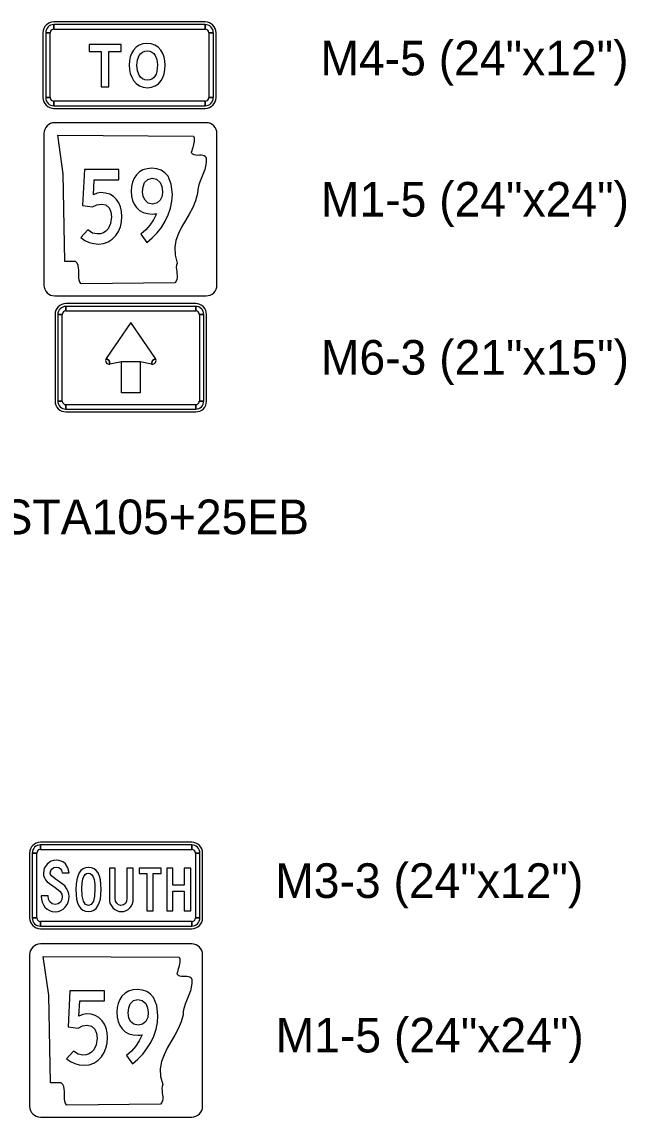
# Model space of a CAD drawing. Extents: x 620856.8 to 620948.6, y 415598.8 to 415658.2.
# Drawn here: x 620865.53 to 620872.52, y 415643.04 to 415655.69 of the extents above; entities that cross this region are included whole.
import ezdxf

# ---------------------------------------------------------------- set-up
doc = ezdxf.new("R2010")
doc.units = 0
doc.layers.add('SIGNS', color=7, linetype='Continuous')

msp = doc.modelspace()

# ---------------------------------------------------------------- linework, layer by layer
at = {"layer": 'SIGNS'}
for p, q in [((620867.653, 415655.689), (620865.903, 415655.689)), ((620865.778, 415655.564), (620865.778, 415654.814)), ((620865.81, 415655.564), (620865.862, 415655.564)), ((620865.903, 415655.605), (620865.903, 415655.657)), ((620867.653, 415655.657), (620867.653, 415655.605)), ((620867.695, 415655.564), (620867.747, 415655.564)), ((620867.778, 415654.814), (620867.778, 415655.564)), ((620865.862, 415654.814), (620865.81, 415654.814)), ((620867.747, 415654.814), (620867.695, 415654.814)), ((620865.903, 415654.72), (620865.903, 415654.772)), ((620865.903, 415654.689), (620867.653, 415654.689)), ((620867.653, 415654.772), (620867.653, 415654.72)), ((620867.664, 415654.524), (620865.914, 415654.524)), ((620865.789, 415654.399), (620865.789, 415652.649)), ((620867.789, 415652.649), (620867.789, 415654.399)), ((620865.789, 415652.649), (620865.789, 415652.649)), ((620865.914, 415652.524), (620867.664, 415652.524)), ((620867.543, 415652.434), (620866.043, 415652.434)), ((620866.043, 415652.35), (620866.043, 415652.402)), ((620867.543, 415652.402), (620867.543, 415652.35)), ((620865.918, 415652.309), (620865.918, 415651.309)), ((620865.949, 415652.309), (620866.001, 415652.309)), ((620867.585, 415652.309), (620867.637, 415652.309)), ((620867.668, 415651.309), (620867.668, 415652.309)), ((620866.543, 415651.777), (620866.508, 415651.8)), ((620866.552, 415651.737), (620866.543, 415651.777)), ((620867.043, 415651.777), (620867.034, 415651.737)), ((620867.078, 415651.8), (620867.043, 415651.777)), ((620866.001, 415651.309), (620865.949, 415651.309)), ((620866.043, 415651.215), (620866.043, 415651.267)), ((620867.543, 415651.267), (620867.543, 415651.215)), ((620867.637, 415651.309), (620867.585, 415651.309)), ((620866.043, 415651.184), (620867.543, 415651.184)), ((620867.498, 415646.213), (620865.748, 415646.213)), ((620865.748, 415646.13), (620865.748, 415646.182)), ((620867.498, 415646.182), (620867.498, 415646.13)), ((620865.623, 415646.088), (620865.623, 415645.338)), ((620865.654, 415646.088), (620865.707, 415646.088)), ((620867.54, 415646.088), (620867.592, 415646.088)), ((620867.623, 415645.338), (620867.623, 415646.088)), ((620865.707, 415645.338), (620865.654, 415645.338)), ((620865.748, 415645.244), (620865.748, 415645.296)), ((620867.498, 415645.296), (620867.498, 415645.244)), ((620867.592, 415645.338), (620867.54, 415645.338)), ((620865.748, 415645.213), (620867.498, 415645.213)), ((620867.498, 415645.037), (620865.748, 415645.037)), ((620865.623, 415644.912), (620865.623, 415643.162)), ((620867.623, 415643.162), (620867.623, 415644.912)), ((620865.623, 415643.162), (620865.623, 415643.162)), ((620865.748, 415643.037), (620867.498, 415643.037))]:
    msp.add_line(p, q, dxfattribs=at)
for points in [[(620865.81, 415655.564), (620865.81, 415654.814), (620865.862, 415654.814), (620865.862, 415655.564), (620865.81, 415655.564), (620865.81, 415655.564)], [(620867.653, 415655.657), (620865.903, 415655.657), (620865.903, 415655.605), (620867.653, 415655.605), (620867.653, 415655.657), (620867.653, 415655.657)], [(620867.747, 415654.814), (620867.747, 415655.564), (620867.695, 415655.564), (620867.695, 415654.814), (620867.747, 415654.814), (620867.747, 415654.814)], [(620866.451, 415654.939), (620866.538, 415654.939), (620866.538, 415655.347), (620866.681, 415655.347), (620866.681, 415655.429), (620866.31, 415655.429), (620866.31, 415655.347), (620866.451, 415655.347)], [(620865.903, 415654.72), (620867.653, 415654.72), (620867.653, 415654.772), (620865.903, 415654.772), (620865.903, 415654.72), (620865.903, 415654.72)], [(620867.519, 415654.37), (620867.524, 415654.351), (620867.525, 415654.331), (620867.525, 415654.312), (620867.522, 415654.293), (620867.518, 415654.274), (620867.514, 415654.255), (620867.508, 415654.236), (620867.502, 415654.218), (620867.497, 415654.199), (620867.492, 415654.181), (620867.506, 415654.165), (620867.523, 415654.156), (620867.543, 415654.152), (620867.565, 415654.151), (620867.586, 415654.152), (620867.607, 415654.152), (620867.626, 415654.15), (620867.642, 415654.144), (620867.655, 415654.132), (620867.663, 415654.112), (620867.664, 415654.066), (620867.658, 415654.024), (620867.648, 415653.983), (620867.633, 415653.945), (620867.618, 415653.906), (620867.602, 415653.869), (620867.587, 415653.83), (620867.575, 415653.79), (620867.566, 415653.749), (620867.564, 415653.705), (620867.542, 415653.623), (620867.508, 415653.544), (620867.468, 415653.469), (620867.424, 415653.394), (620867.38, 415653.319), (620867.343, 415653.243), (620867.315, 415653.165), (620867.3, 415653.082), (620867.304, 415652.995), (620867.329, 415652.901), (620867.322, 415652.878), (620867.319, 415652.854), (620867.32, 415652.83), (620867.323, 415652.806), (620867.326, 415652.782), (620867.329, 415652.759), (620867.329, 415652.736), (620867.326, 415652.714), (620867.318, 415652.693), (620867.302, 415652.673), (620866.219, 415652.663), (620866.204, 415652.683), (620866.195, 415652.707), (620866.192, 415652.733), (620866.191, 415652.761), (620866.192, 415652.791), (620866.192, 415652.82), (620866.19, 415652.849), (620866.185, 415652.876), (620866.174, 415652.901), (620866.155, 415652.921), (620866.029, 415652.921), (620866.011, 415653.933), (620865.948, 415654.38), (620867.519, 415654.37), (620867.519, 415654.37)], [(620866.214, 415653.198), (620866.262, 415653.165), (620866.312, 415653.142), (620866.364, 415653.128), (620866.419, 415653.123), (620866.478, 415653.129), (620866.531, 415653.147), (620866.578, 415653.178), (620866.619, 415653.221), (620866.65, 415653.268), (620866.672, 415653.321), (620866.685, 415653.379), (620866.689, 415653.442), (620866.685, 415653.499), (620866.674, 415653.551), (620866.655, 415653.597), (620866.627, 415653.638), (620866.591, 415653.672), (620866.549, 415653.697), (620866.499, 415653.712), (620866.445, 415653.717), (620866.404, 415653.711), (620866.36, 415653.691), (620866.369, 415653.866), (620866.656, 415653.866), (620866.656, 415653.982), (620866.256, 415653.982), (620866.235, 415653.566), (620866.352, 415653.551), (620866.4, 415653.577), (620866.453, 415653.585), (620866.505, 415653.574), (620866.543, 415653.539), (620866.563, 415653.493), (620866.57, 415653.436), (620866.56, 415653.361), (620866.53, 415653.3), (620866.505, 415653.273), (620866.477, 415653.254), (620866.443, 415653.242), (620866.406, 415653.239), (620866.349, 415653.25), (620866.295, 415653.286)], [(620867.543, 415652.402), (620866.043, 415652.402), (620866.043, 415652.35), (620867.543, 415652.35), (620867.543, 415652.402), (620867.543, 415652.402)], [(620865.949, 415652.309), (620865.949, 415651.309), (620866.001, 415651.309), (620866.001, 415652.309), (620865.949, 415652.309), (620865.949, 415652.309)], [(620867.637, 415651.309), (620867.637, 415652.309), (620867.585, 415652.309), (620867.585, 415651.309), (620867.637, 415651.309), (620867.637, 415651.309)], [(620866.793, 415652.215), (620866.508, 415651.8), (620866.543, 415651.777), (620866.552, 415651.737), (620866.684, 415651.767), (620866.903, 415651.767), (620867.034, 415651.737), (620867.043, 415651.777), (620867.078, 415651.8), (620866.793, 415652.215), (620866.793, 415652.215)], [(620866.903, 415651.402), (620866.684, 415651.402), (620866.684, 415651.767), (620866.903, 415651.767), (620866.903, 415651.402), (620866.903, 415651.402)], [(620866.043, 415651.215), (620867.543, 415651.215), (620867.543, 415651.267), (620866.043, 415651.267), (620866.043, 415651.215), (620866.043, 415651.215)], [(620867.498, 415646.182), (620865.748, 415646.182), (620865.748, 415646.13), (620867.498, 415646.13), (620867.498, 415646.182), (620867.498, 415646.182)], [(620865.654, 415646.088), (620865.654, 415645.338), (620865.707, 415645.338), (620865.707, 415646.088), (620865.654, 415646.088), (620865.654, 415646.088)], [(620867.592, 415645.338), (620867.592, 415646.088), (620867.54, 415646.088), (620867.54, 415645.338), (620867.592, 415645.338), (620867.592, 415645.338)], [(620865.757, 415645.593), (620865.757, 415645.588), (620865.759, 415645.553), (620865.768, 415645.521), (620865.782, 415645.491), (620865.801, 415645.464), (620865.826, 415645.44), (620865.854, 415645.424), (620865.885, 415645.414), (620865.919, 415645.41), (620865.953, 415645.413), (620865.984, 415645.423), (620866.011, 415645.44), (620866.036, 415645.463), (620866.055, 415645.489), (620866.069, 415645.518), (620866.077, 415645.55), (620866.08, 415645.585), (620866.077, 415645.618), (620866.067, 415645.65), (620866.051, 415645.679), (620866.029, 415645.708), (620865.985, 415645.745), (620865.919, 415645.79), (620865.875, 415645.823), (620865.866, 415645.84), (620865.862, 415645.859), (620865.867, 415645.885), (620865.883, 415645.906), (620865.905, 415645.921), (620865.932, 415645.926), (620865.96, 415645.921), (620865.981, 415645.907), (620865.992, 415645.888), (620866, 415645.859), (620866.08, 415645.859), (620866.067, 415645.918), (620866.037, 415645.963), (620866.014, 415645.981), (620865.989, 415645.994), (620865.961, 415646.002), (620865.929, 415646.005), (620865.9, 415646.002), (620865.873, 415645.994), (620865.848, 415645.98), (620865.826, 415645.96), (620865.793, 415645.912), (620865.783, 415645.857), (620865.785, 415645.828), (620865.794, 415645.802), (620865.807, 415645.777), (620865.827, 415645.755), (620865.919, 415645.689), (620865.954, 415645.663), (620865.975, 415645.643), (620865.994, 415645.614), (620866.001, 415645.584), (620865.995, 415645.55), (620865.979, 415645.521), (620865.952, 415645.5), (620865.919, 415645.493), (620865.884, 415645.501), (620865.857, 415645.525), (620865.841, 415645.556), (620865.836, 415645.593)], [(620866.546, 415645.912), (620866.546, 415645.557), (620866.548, 415645.528), (620866.556, 415645.501), (620866.569, 415645.477), (620866.587, 415645.454), (620866.608, 415645.436), (620866.631, 415645.422), (620866.657, 415645.414), (620866.686, 415645.412), (620866.714, 415645.414), (620866.739, 415645.423), (620866.763, 415645.437), (620866.784, 415645.457), (620866.801, 415645.479), (620866.813, 415645.504), (620866.82, 415645.53), (620866.822, 415645.558), (620866.822, 415645.912), (620866.747, 415645.912), (620866.747, 415645.561), (620866.743, 415645.53), (620866.73, 415645.506), (620866.708, 415645.488), (620866.679, 415645.483), (620866.651, 415645.489), (620866.63, 415645.507), (620866.617, 415645.532), (620866.613, 415645.561), (620866.613, 415645.912)], [(620866.98, 415645.421), (620867.051, 415645.421), (620867.051, 415645.85), (620867.142, 415645.85), (620867.142, 415645.912), (620866.89, 415645.912), (620866.89, 415645.85), (620866.98, 415645.85)], [(620867.21, 415645.421), (620867.277, 415645.421), (620867.277, 415645.646), (620867.411, 415645.646), (620867.411, 415645.421), (620867.486, 415645.421), (620867.486, 415645.912), (620867.411, 415645.912), (620867.411, 415645.715), (620867.277, 415645.715), (620867.277, 415645.912), (620867.21, 415645.912)], [(620865.748, 415645.244), (620867.498, 415645.244), (620867.498, 415645.296), (620865.748, 415645.296), (620865.748, 415645.244), (620865.748, 415645.244)], [(620867.353, 415644.883), (620867.358, 415644.864), (620867.359, 415644.844), (620867.359, 415644.825), (620867.356, 415644.806), (620867.352, 415644.787), (620867.348, 415644.768), (620867.342, 415644.749), (620867.336, 415644.731), (620867.331, 415644.713), (620867.326, 415644.694), (620867.34, 415644.678), (620867.357, 415644.669), (620867.377, 415644.665), (620867.399, 415644.665), (620867.42, 415644.665), (620867.441, 415644.666), (620867.46, 415644.663), (620867.476, 415644.657), (620867.489, 415644.645), (620867.497, 415644.625), (620867.498, 415644.579), (620867.492, 415644.537), (620867.482, 415644.496), (620867.467, 415644.458), (620867.452, 415644.42), (620867.436, 415644.382), (620867.421, 415644.343), (620867.409, 415644.304), (620867.4, 415644.262), (620867.398, 415644.218), (620867.376, 415644.136), (620867.342, 415644.058), (620867.302, 415643.982), (620867.257, 415643.907), (620867.214, 415643.833), (620867.177, 415643.757), (620867.149, 415643.678), (620867.134, 415643.596), (620867.138, 415643.508), (620867.163, 415643.415), (620867.156, 415643.391), (620867.153, 415643.368), (620867.154, 415643.344), (620867.157, 415643.319), (620867.16, 415643.296), (620867.163, 415643.272), (620867.163, 415643.249), (620867.16, 415643.227), (620867.152, 415643.206), (620867.136, 415643.186), (620866.052, 415643.176), (620866.038, 415643.196), (620866.029, 415643.22), (620866.026, 415643.246), (620866.025, 415643.275), (620866.026, 415643.304), (620866.026, 415643.334), (620866.024, 415643.363), (620866.019, 415643.39), (620866.008, 415643.414), (620865.989, 415643.434), (620865.863, 415643.434), (620865.845, 415644.446), (620865.781, 415644.893), (620867.353, 415644.883), (620867.353, 415644.883)], [(620866.048, 415643.711), (620866.096, 415643.678), (620866.146, 415643.655), (620866.198, 415643.641), (620866.253, 415643.637), (620866.312, 415643.643), (620866.365, 415643.661), (620866.412, 415643.691), (620866.453, 415643.734), (620866.484, 415643.782), (620866.505, 415643.834), (620866.519, 415643.892), (620866.523, 415643.955), (620866.519, 415644.012), (620866.508, 415644.064), (620866.489, 415644.111), (620866.461, 415644.151), (620866.425, 415644.186), (620866.382, 415644.211), (620866.333, 415644.226), (620866.279, 415644.231), (620866.238, 415644.224), (620866.194, 415644.204), (620866.203, 415644.379), (620866.49, 415644.379), (620866.49, 415644.495), (620866.09, 415644.495), (620866.069, 415644.079), (620866.186, 415644.064), (620866.234, 415644.09), (620866.287, 415644.099), (620866.339, 415644.087), (620866.377, 415644.052), (620866.397, 415644.006), (620866.404, 415643.949), (620866.394, 415643.874), (620866.364, 415643.813), (620866.339, 415643.786), (620866.31, 415643.767), (620866.277, 415643.756), (620866.24, 415643.752), (620866.183, 415643.764), (620866.129, 415643.799)]]:
    msp.add_lwpolyline(points, close=True, dxfattribs=at)
for points in [[(620867.19, 415655.188), (620867.187, 415655.238), (620867.178, 415655.283), (620867.162, 415655.324), (620867.139, 415655.361), (620867.108, 415655.395), (620867.071, 415655.419), (620867.028, 415655.434), (620866.98, 415655.439), (620866.932, 415655.434), (620866.89, 415655.419), (620866.854, 415655.395), (620866.824, 415655.361), (620866.802, 415655.325), (620866.787, 415655.285), (620866.778, 415655.239), (620866.775, 415655.19), (620866.778, 415655.139), (620866.787, 415655.092), (620866.803, 415655.05), (620866.824, 415655.012), (620866.855, 415654.976), (620866.892, 415654.95), (620866.935, 415654.934), (620866.984, 415654.929), (620867.032, 415654.934), (620867.075, 415654.95), (620867.112, 415654.975), (620867.142, 415655.011), (620867.163, 415655.048), (620867.178, 415655.09), (620867.187, 415655.137), (620867.19, 415655.188)], [(620867.101, 415655.194), (620867.099, 415655.153), (620867.094, 415655.117), (620867.085, 415655.086), (620867.072, 415655.061), (620867.056, 415655.042), (620867.035, 415655.028), (620867.011, 415655.02), (620866.984, 415655.017), (620866.954, 415655.021), (620866.928, 415655.031), (620866.906, 415655.049), (620866.889, 415655.074), (620866.87, 415655.124), (620866.864, 415655.188), (620866.87, 415655.249), (620866.889, 415655.299), (620866.907, 415655.323), (620866.929, 415655.34), (620866.954, 415655.351), (620866.984, 415655.354), (620867.013, 415655.351), (620867.037, 415655.341), (620867.058, 415655.325), (620867.076, 415655.302), (620867.095, 415655.253), (620867.101, 415655.194)], [(620865.914, 415654.524), (620865.914, 415654.524)], [(620867.664, 415654.524), (620867.664, 415654.524)], [(620865.789, 415654.399), (620865.789, 415654.399)], [(620866.91, 415653.235), (620866.978, 415653.14), (620867.041, 415653.193), (620867.097, 415653.251), (620867.146, 415653.315), (620867.19, 415653.385), (620867.226, 415653.461), (620867.252, 415653.538), (620867.268, 415653.616), (620867.273, 415653.695), (620867.26, 415653.814), (620867.223, 415653.905), (620867.188, 415653.946), (620867.145, 415653.975), (620867.094, 415653.992), (620867.035, 415653.998), (620866.981, 415653.993), (620866.933, 415653.979), (620866.892, 415653.955), (620866.857, 415653.921), (620866.831, 415653.882), (620866.812, 415653.838), (620866.801, 415653.789), (620866.798, 415653.735), (620866.801, 415653.677), (620866.813, 415653.626), (620866.832, 415653.582), (620866.859, 415653.544), (620866.895, 415653.511), (620866.937, 415653.488), (620866.987, 415653.474), (620867.044, 415653.469), (620867.068, 415653.471), (620867.091, 415653.472), (620867.089, 415653.472), (620867.055, 415653.403), (620867.014, 415653.341), (620866.966, 415653.285), (620866.91, 415653.235)], [(620867.161, 415653.731), (620867.154, 415653.675), (620867.133, 415653.63), (620867.096, 415653.597), (620867.044, 415653.585), (620866.994, 415653.596), (620866.957, 415653.628), (620866.936, 415653.672), (620866.93, 415653.727), (620866.935, 415653.785), (620866.953, 415653.832), (620866.989, 415653.87), (620867.04, 415653.883), (620867.091, 415653.871), (620867.131, 415653.835), (620867.153, 415653.788), (620867.161, 415653.731)], [(620865.914, 415652.524), (620865.914, 415652.524)], [(620867.664, 415652.524), (620867.664, 415652.524)], [(620866.45, 415645.667), (620866.448, 415645.727), (620866.441, 415645.778), (620866.43, 415645.822), (620866.414, 415645.858), (620866.393, 415645.885), (620866.368, 415645.905), (620866.339, 415645.917), (620866.305, 415645.921), (620866.271, 415645.917), (620866.241, 415645.905), (620866.216, 415645.885), (620866.195, 415645.858), (620866.179, 415645.822), (620866.168, 415645.778), (620866.161, 415645.727), (620866.158, 415645.667), (620866.16, 415645.607), (620866.167, 415645.555), (620866.178, 415645.511), (620866.194, 415645.476), (620866.214, 415645.447), (620866.239, 415645.428), (620866.268, 415645.416), (620866.302, 415645.412), (620866.337, 415645.416), (620866.367, 415645.428), (620866.392, 415645.447), (620866.413, 415645.476), (620866.429, 415645.511), (620866.441, 415645.555), (620866.448, 415645.607), (620866.45, 415645.667)], [(620866.379, 415645.67), (620866.375, 415645.588), (620866.36, 415645.53), (620866.336, 415645.495), (620866.303, 415645.483), (620866.269, 415645.495), (620866.245, 415645.533), (620866.23, 415645.595), (620866.226, 415645.682), (620866.229, 415645.74), (620866.238, 415645.788), (620866.249, 415645.817), (620866.264, 415645.839), (620866.282, 415645.851), (620866.303, 415645.855), (620866.324, 415645.851), (620866.342, 415645.837), (620866.356, 415645.814), (620866.368, 415645.781), (620866.376, 415645.73), (620866.379, 415645.67)], [(620865.748, 415645.037), (620865.748, 415645.037)], [(620867.498, 415645.037), (620867.498, 415645.037)], [(620865.623, 415644.912), (620865.623, 415644.912)], [(620866.744, 415643.748), (620866.812, 415643.653), (620866.875, 415643.706), (620866.931, 415643.764), (620866.98, 415643.828), (620867.024, 415643.898), (620867.06, 415643.974), (620867.086, 415644.052), (620867.102, 415644.129), (620867.107, 415644.208), (620867.094, 415644.327), (620867.057, 415644.418), (620867.022, 415644.459), (620866.979, 415644.488), (620866.928, 415644.505), (620866.869, 415644.511), (620866.815, 415644.507), (620866.767, 415644.492), (620866.726, 415644.468), (620866.691, 415644.434), (620866.665, 415644.395), (620866.646, 415644.351), (620866.635, 415644.302), (620866.632, 415644.248), (620866.635, 415644.191), (620866.647, 415644.14), (620866.666, 415644.095), (620866.693, 415644.057), (620866.729, 415644.024), (620866.771, 415644.001), (620866.821, 415643.987), (620866.878, 415643.982), (620866.902, 415643.984), (620866.925, 415643.986), (620866.923, 415643.986), (620866.889, 415643.917), (620866.848, 415643.854), (620866.8, 415643.798), (620866.744, 415643.748)], [(620866.995, 415644.245), (620866.988, 415644.188), (620866.967, 415644.143), (620866.93, 415644.11), (620866.878, 415644.099), (620866.828, 415644.109), (620866.791, 415644.142), (620866.77, 415644.185), (620866.764, 415644.24), (620866.769, 415644.298), (620866.787, 415644.345), (620866.823, 415644.383), (620866.874, 415644.396), (620866.925, 415644.384), (620866.965, 415644.349), (620866.987, 415644.301), (620866.995, 415644.245)], [(620865.748, 415643.037), (620865.748, 415643.037)], [(620867.498, 415643.037), (620867.498, 415643.037)]]:
    msp.add_lwpolyline(points, dxfattribs=at)
for centre, radius, start, end in [((620865.903, 415655.564), 0.125, 90.0002, 179.9998), ((620867.653, 415655.564), 0.125, 0, 90.0002), ((620865.903, 415655.564), 0.0937, 90.0002, 179.9998), ((620865.903, 415655.564), 0.0417, 90.0002, 179.9998), ((620867.653, 415655.564), 0.0937, 0, 90.0002), ((620867.653, 415655.564), 0.0417, 0, 90.0002), ((620865.903, 415654.814), 0.125, 179.9998, 270.0001), ((620865.903, 415654.814), 0.0937, 179.9998, 270.0001), ((620865.903, 415654.814), 0.0417, 179.9998, 270.0001), ((620867.653, 415654.814), 0.125, 270.0001, 0.0003), ((620867.653, 415654.814), 0.0937, 270.0001, 0.0003), ((620867.653, 415654.814), 0.0417, 270.0001, 0.0003), ((620865.914, 415654.399), 0.125, 90.0002, 179.9998), ((620867.664, 415654.399), 0.125, 360, 90), ((620865.914, 415652.649), 0.125, 180, 270), ((620867.664, 415652.649), 0.125, 270.0001, 0.0003), ((620866.043, 415652.309), 0.125, 90.0002, 179.9998), ((620866.043, 415652.309), 0.0937, 90.0002, 179.9998), ((620867.543, 415652.309), 0.125, 0, 90.0002), ((620867.543, 415652.309), 0.0937, 0, 90.0002), ((620866.043, 415652.309), 0.0417, 90.0002, 179.9998), ((620867.543, 415652.309), 0.0417, 0, 90.0002), ((620866.543, 415651.777), 0.0417, 147.7246, 282.9506), ((620867.043, 415651.777), 0.0417, 257.0495, 32.2756), ((620866.043, 415651.309), 0.125, 179.9998, 270.0001), ((620866.043, 415651.309), 0.0937, 179.9998, 270.0001), ((620866.043, 415651.309), 0.0417, 179.9998, 270.0001), ((620867.543, 415651.309), 0.0937, 270.0001, 0.0003), ((620867.543, 415651.309), 0.0417, 270.0001, 0.0003), ((620867.543, 415651.309), 0.125, 270.0001, 0.0003), ((620865.748, 415646.088), 0.125, 90.0002, 179.9998), ((620865.748, 415646.088), 0.0937, 90.0002, 179.9998), ((620867.498, 415646.088), 0.125, 360, 90.0002), ((620867.498, 415646.088), 0.0937, 360, 90.0002), ((620865.748, 415646.088), 0.0417, 90.0002, 179.9998), ((620867.498, 415646.088), 0.0417, 360, 90.0002), ((620865.748, 415645.338), 0.125, 179.9998, 270.0001), ((620865.748, 415645.338), 0.0937, 179.9998, 270.0001), ((620865.748, 415645.338), 0.0417, 179.9998, 270.0001), ((620867.498, 415645.338), 0.125, 270.0001, 0.0003), ((620867.498, 415645.338), 0.0937, 270.0001, 0.0003), ((620867.498, 415645.338), 0.0417, 270.0001, 0.0003), ((620865.748, 415644.912), 0.125, 90.0002, 179.9998), ((620867.498, 415644.912), 0.125, 360, 90), ((620865.748, 415643.162), 0.125, 180, 270), ((620867.498, 415643.162), 0.125, 270.0001, 0.0003)]:
    msp.add_arc(centre, radius, start, end, dxfattribs=at)

# ---------------------------------------------------------------- texts
for s, p in [('M4-5 (24"x12")', (620868.985, 415655.071)), ('M1-5 (24"x24")', (620868.99, 415653.44)), ('M6-3 (21"x15")', (620868.99, 415651.614)), ('SS-ACC-17-STA105+25EB', (620862.327, 415649.771)), ('M3-3 (24"x12")', (620868.462, 415645.569)), ('M1-5 (24"x24")', (620868.467, 415643.784))]:
    msp.add_text(s, height=0.4, rotation=0, dxfattribs=at).set_placement(p)

doc.saveas('drawing.dxf')
